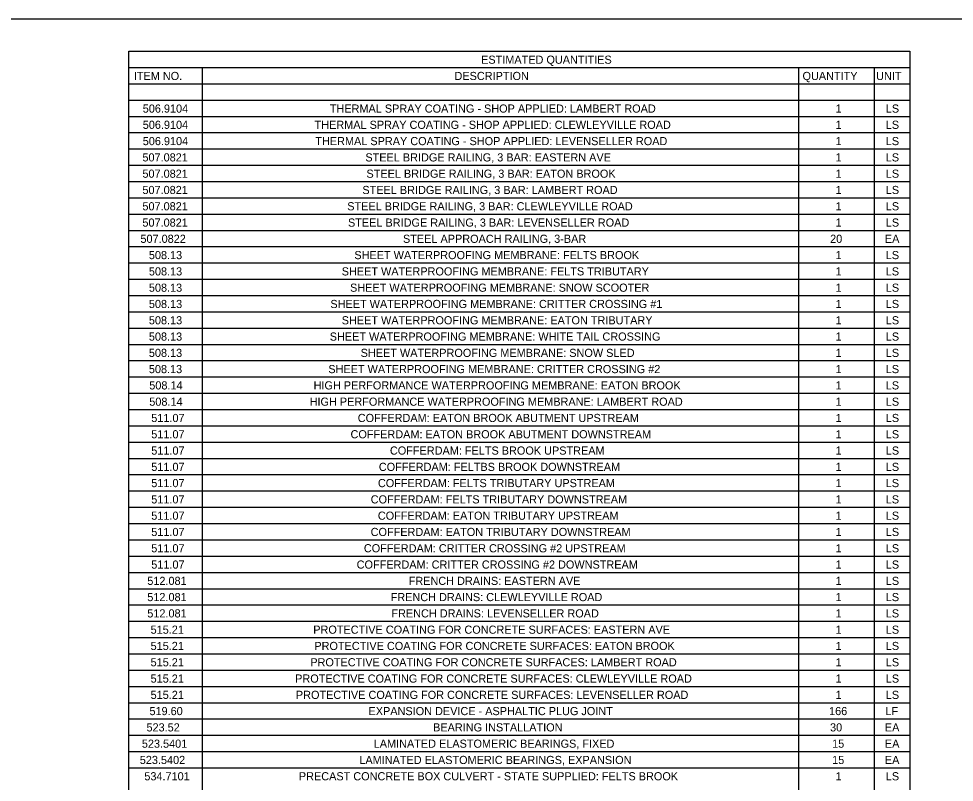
# Model space of a CAD drawing. Extents: x -18.7 to 5.6, y -2.7 to 5.1.
# Drawn here: x -16.637 to -15.505, y 3.091 to 4.014 of the extents above; entities that cross this region are included whole.
import ezdxf

# ---------------------------------------------------------------- set-up
doc = ezdxf.new("R2010")
doc.units = 0
doc.layers.add('ANNOTATION', color=7, linetype='Continuous')
doc.layers.add('BORDER', color=7, linetype='Continuous')

msp = doc.modelspace()

# ---------------------------------------------------------------- linework, layer by layer
at = {"layer": 'ANNOTATION'}
msp.add_lwpolyline([(-17.663, 4.0141), (-13.3075, 4.0141), (-13.3075, 2.1719), (-17.663, 2.1719)], close=True, dxfattribs=at)
at = {"layer": 'BORDER'}
for p, q in [((-16.5036, 3.9551), (-15.5593, 3.9551)), ((-16.415, 3.9551), (-16.415, 2.2424)), ((-15.6937, 3.9551), (-15.6937, 2.2424)), ((-15.6023, 3.9551), (-15.6023, 2.2424)), ((-16.5036, 3.9354), (-15.5593, 3.9354)), ((-16.5036, 3.9157), (-15.5593, 3.9157)), ((-16.5036, 3.896), (-15.5593, 3.896)), ((-16.5036, 3.8764), (-15.5593, 3.8764)), ((-16.5036, 3.8567), (-15.5593, 3.8567)), ((-16.5036, 3.837), (-15.5593, 3.837)), ((-16.5036, 3.8173), (-15.5593, 3.8173)), ((-16.5036, 3.7976), (-15.5593, 3.7976)), ((-16.5036, 3.7779), (-15.5593, 3.7779)), ((-16.5036, 3.7582), (-15.5593, 3.7582)), ((-16.5036, 3.7386), (-15.5593, 3.7386)), ((-16.5036, 3.7189), (-15.5593, 3.7189)), ((-16.5036, 3.6992), (-15.5593, 3.6992)), ((-16.5036, 3.6795), (-15.5593, 3.6795)), ((-16.5036, 3.6598), (-15.5593, 3.6598)), ((-16.5036, 3.6401), (-15.5593, 3.6401)), ((-16.5036, 3.6204), (-15.5593, 3.6204)), ((-16.5036, 3.6008), (-15.5593, 3.6008)), ((-16.5036, 3.5811), (-15.5593, 3.5811)), ((-16.5036, 3.5614), (-15.5593, 3.5614)), ((-16.5036, 3.5417), (-15.5593, 3.5417)), ((-16.5036, 3.522), (-15.5593, 3.522)), ((-16.5036, 3.5023), (-15.5593, 3.5023)), ((-16.5036, 3.4826), (-15.5593, 3.4826)), ((-16.5036, 3.463), (-15.5593, 3.463)), ((-16.5036, 3.4433), (-15.5593, 3.4433)), ((-16.5036, 3.4236), (-15.5593, 3.4236)), ((-16.5036, 3.4039), (-15.5593, 3.4039)), ((-16.5036, 3.3842), (-15.5593, 3.3842)), ((-16.5036, 3.3645), (-15.5593, 3.3645)), ((-16.5036, 3.3448), (-15.5593, 3.3448)), ((-16.5036, 3.3251), (-15.5593, 3.3251)), ((-16.5036, 3.3055), (-15.5593, 3.3055)), ((-16.5036, 3.2858), (-15.5593, 3.2858)), ((-16.5036, 3.2661), (-15.5593, 3.2661)), ((-16.5036, 3.2464), (-15.5593, 3.2464)), ((-16.5036, 3.2267), (-15.5593, 3.2267)), ((-16.5036, 3.207), (-15.5593, 3.207)), ((-16.5036, 3.1873), (-15.5593, 3.1873)), ((-16.5036, 3.1677), (-15.5593, 3.1677)), ((-16.5036, 3.148), (-15.5593, 3.148)), ((-16.5036, 3.1283), (-15.5593, 3.1283)), ((-16.5036, 3.1086), (-15.5593, 3.1086))]:
    msp.add_line(p, q, dxfattribs=at)
msp.add_lwpolyline([(-16.5036, 3.9748), (-15.5593, 3.9748), (-15.5593, 2.2424), (-16.5036, 2.2424)], close=True, dxfattribs=at)

# ---------------------------------------------------------------- texts
at = {"layer": 'ANNOTATION'}
for s, height, p in [('506.9104', 0.00984, (-16.4869, 3.9006)), ('THERMAL SPRAY COATING - SHOP APPLIED: LAMBERT ROAD', 0.009843, (-16.2607, 3.9006)), ('1', 0.00984, (-15.649, 3.9006)), ('LS', 0.00984, (-15.5883, 3.9006)), ('506.9104', 0.00984, (-16.4869, 3.881)), ('THERMAL SPRAY COATING - SHOP APPLIED: CLEWLEYVILLE ROAD', 0.009843, (-16.2791, 3.881)), ('1', 0.00984, (-15.649, 3.881)), ('LS', 0.00984, (-15.5883, 3.881)), ('506.9104', 0.00984, (-16.4869, 3.8613)), ('THERMAL SPRAY COATING - SHOP APPLIED: LEVENSELLER ROAD', 0.009843, (-16.2782, 3.8613)), ('1', 0.00984, (-15.649, 3.8613)), ('LS', 0.00984, (-15.5883, 3.8613)), ('507.0821', 0.00984, (-16.4873, 3.8416)), ('STEEL BRIDGE RAILING, 3 BAR: EASTERN AVE', 0.009843, (-16.2177, 3.8416)), ('1', 0.00984, (-15.649, 3.8416)), ('LS', 0.00984, (-15.5883, 3.8416)), ('507.0821', 0.00984, (-16.4873, 3.8219)), ('STEEL BRIDGE RAILING, 3 BAR: EATON BROOK', 0.009843, (-16.2164, 3.8219)), ('1', 0.00984, (-15.649, 3.8219)), ('LS', 0.00984, (-15.5883, 3.8219)), ('507.0821', 0.00984, (-16.4873, 3.8022)), ('STEEL BRIDGE RAILING, 3 BAR: LAMBERT ROAD', 0.009843, (-16.2213, 3.8022)), ('1', 0.00984, (-15.649, 3.8022)), ('LS', 0.00984, (-15.5883, 3.8022)), ('507.0821', 0.00984, (-16.4873, 3.7825)), ('STEEL BRIDGE RAILING, 3 BAR: CLEWLEYVILLE ROAD', 0.009843, (-16.2396, 3.7825)), ('1', 0.00984, (-15.649, 3.7825)), ('LS', 0.00984, (-15.5883, 3.7825)), ('507.0821', 0.00984, (-16.4873, 3.7628)), ('STEEL BRIDGE RAILING, 3 BAR: LEVENSELLER ROAD', 0.009843, (-16.2387, 3.7628)), ('1', 0.00984, (-15.649, 3.7628)), ('LS', 0.00984, (-15.5883, 3.7628)), ('507.0822', 0.00984, (-16.4897, 3.7432)), ('STEEL APPROACH RAILING, 3-BAR', 0.009843, (-16.1722, 3.7432)), ('20', 0.00984, (-15.6556, 3.7432)), ('EA', 0.00984, (-15.5894, 3.7432)), ('508.13', 0.00984, (-16.4795, 3.7235)), ('SHEET WATERPROOFING MEMBRANE: FELTS BROOK', 0.009843, (-16.231, 3.7235)), ('1', 0.00984, (-15.649, 3.7235)), ('LS', 0.00984, (-15.5883, 3.7235)), ('508.13', 0.00984, (-16.4795, 3.7038)), ('SHEET WATERPROOFING MEMBRANE: FELTS TRIBUTARY', 0.009843, (-16.2463, 3.7038)), ('1', 0.00984, (-15.649, 3.7038)), ('LS', 0.00984, (-15.5883, 3.7038)), ('508.13', 0.00984, (-16.4795, 3.6841)), ('SHEET WATERPROOFING MEMBRANE: SNOW SCOOTER', 0.009843, (-16.2362, 3.6841)), ('1', 0.00984, (-15.649, 3.6841)), ('LS', 0.00984, (-15.5883, 3.6841)), ('508.13', 0.00984, (-16.4795, 3.6644)), ('SHEET WATERPROOFING MEMBRANE: CRITTER CROSSING #1', 0.009843, (-16.26, 3.6644)), ('1', 0.00984, (-15.649, 3.6644)), ('LS', 0.00984, (-15.5883, 3.6644)), ('508.13', 0.00984, (-16.4795, 3.6447)), ('SHEET WATERPROOFING MEMBRANE: EATON TRIBUTARY', 0.009843, (-16.2463, 3.6447)), ('LS', 0.00984, (-15.5883, 3.6447)), ('1', 0.00984, (-15.649, 3.6447)), ('508.13', 0.00984, (-16.4795, 3.625)), ('SHEET WATERPROOFING MEMBRANE: WHITE TAIL CROSSING', 0.009843, (-16.2608, 3.625)), ('1', 0.00984, (-15.649, 3.625)), ('LS', 0.00984, (-15.5883, 3.625)), ('508.13', 0.00984, (-16.4795, 3.6053)), ('SHEET WATERPROOFING MEMBRANE: SNOW SLED', 0.009843, (-16.2234, 3.6053)), ('1', 0.00984, (-15.649, 3.6053)), ('LS', 0.00984, (-15.5883, 3.6053)), ('508.13', 0.00984, (-16.4795, 3.5857)), ('SHEET WATERPROOFING MEMBRANE: CRITTER CROSSING #2', 0.009843, (-16.2625, 3.5857)), ('1', 0.00984, (-15.649, 3.5857)), ('LS', 0.00984, (-15.5883, 3.5857)), ('508.14', 0.00984, (-16.479, 3.566)), ('HIGH PERFORMANCE WATERPROOFING MEMBRANE: EATON BROOK', 0.009843, (-16.2803, 3.566)), ('1', 0.00984, (-15.649, 3.566)), ('LS', 0.00984, (-15.5883, 3.566)), ('508.14', 0.00984, (-16.479, 3.5463)), ('HIGH PERFORMANCE WATERPROOFING MEMBRANE: LAMBERT ROAD', 0.009843, (-16.2851, 3.5463)), ('1', 0.00984, (-15.649, 3.5463)), ('LS', 0.00984, (-15.5883, 3.5463)), ('511.07', 0.00984, (-16.4766, 3.5266)), ('COFFERDAM: EATON BROOK ABUTMENT UPSTREAM', 0.009843, (-16.2269, 3.5266)), ('1', 0.00984, (-15.649, 3.5266)), ('LS', 0.00984, (-15.5883, 3.5266)), ('511.07', 0.00984, (-16.4766, 3.5069)), ('COFFERDAM: EATON BROOK ABUTMENT DOWNSTREAM', 0.009843, (-16.2356, 3.5069)), ('1', 0.00984, (-15.649, 3.5069)), ('LS', 0.00984, (-15.5883, 3.5069)), ('511.07', 0.00984, (-16.4766, 3.4872)), ('COFFERDAM: FELTS BROOK UPSTREAM', 0.009843, (-16.188, 3.4872)), ('1', 0.00984, (-15.649, 3.4872)), ('LS', 0.00984, (-15.5883, 3.4872)), ('511.07', 0.00984, (-16.4766, 3.4675)), ('COFFERDAM: FELTBS BROOK DOWNSTREAM', 0.009843, (-16.2014, 3.4675)), ('1', 0.00984, (-15.649, 3.4675)), ('LS', 0.00984, (-15.5883, 3.4675)), ('511.07', 0.00984, (-16.4766, 3.4479)), ('COFFERDAM: FELTS TRIBUTARY UPSTREAM', 0.009843, (-16.2025, 3.4479)), ('1', 0.00984, (-15.649, 3.4479)), ('LS', 0.00984, (-15.5883, 3.4479)), ('511.07', 0.00984, (-16.4766, 3.4282)), ('COFFERDAM: FELTS TRIBUTARY DOWNSTREAM', 0.009843, (-16.2112, 3.4282)), ('1', 0.00984, (-15.649, 3.4282)), ('LS', 0.00984, (-15.5883, 3.4282)), ('511.07', 0.00984, (-16.4766, 3.4085)), ('COFFERDAM: EATON TRIBUTARY UPSTREAM', 0.009843, (-16.2026, 3.4085)), ('1', 0.00984, (-15.649, 3.4085)), ('LS', 0.00984, (-15.5883, 3.4085)), ('511.07', 0.00984, (-16.4766, 3.3888)), ('COFFERDAM: EATON TRIBUTARY DOWNSTREAM', 0.009843, (-16.2113, 3.3888)), ('1', 0.00984, (-15.649, 3.3888)), ('LS', 0.00984, (-15.5883, 3.3888)), ('511.07', 0.00984, (-16.4766, 3.3691)), ('COFFERDAM: CRITTER CROSSING #2 UPSTREAM', 0.009843, (-16.2195, 3.3691)), ('1', 0.00984, (-15.649, 3.3691)), ('LS', 0.00984, (-15.5883, 3.3691)), ('511.07', 0.00984, (-16.4766, 3.3494)), ('COFFERDAM: CRITTER CROSSING #2 DOWNSTREAM', 0.009843, (-16.2282, 3.3494)), ('1', 0.00984, (-15.649, 3.3494)), ('LS', 0.00984, (-15.5883, 3.3494)), ('512.081', 0.00984, (-16.4814, 3.3297)), ('FRENCH DRAINS: EASTERN AVE', 0.009843, (-16.1653, 3.3297)), ('1', 0.00984, (-15.649, 3.3297)), ('LS', 0.00984, (-15.5883, 3.3297)), ('512.081', 0.00984, (-16.4814, 3.3101)), ('FRENCH DRAINS: CLEWLEYVILLE ROAD', 0.009843, (-16.1871, 3.3101)), ('1', 0.00984, (-15.649, 3.3101)), ('LS', 0.00984, (-15.5883, 3.3101)), ('512.081', 0.00984, (-16.4814, 3.2904)), ('FRENCH DRAINS: LEVENSELLER ROAD', 0.009843, (-16.1862, 3.2904)), ('1', 0.00984, (-15.649, 3.2904)), ('LS', 0.00984, (-15.5883, 3.2904)), ('515.21', 0.00984, (-16.4774, 3.2707)), ('PROTECTIVE COATING FOR CONCRETE SURFACES: EASTERN AVE', 0.009843, (-16.2807, 3.2707)), ('1', 0.00984, (-15.649, 3.2707)), ('LS', 0.00984, (-15.5883, 3.2707)), ('515.21', 0.00984, (-16.4774, 3.251)), ('PROTECTIVE COATING FOR CONCRETE SURFACES: EATON BROOK', 0.009843, (-16.2794, 3.251)), ('1', 0.00984, (-15.649, 3.251)), ('LS', 0.00984, (-15.5883, 3.251)), ('515.21', 0.00984, (-16.4774, 3.2313)), ('PROTECTIVE COATING FOR CONCRETE SURFACES: LAMBERT ROAD', 0.009843, (-16.2843, 3.2313)), ('1', 0.00984, (-15.649, 3.2313)), ('LS', 0.00984, (-15.5883, 3.2313)), ('515.21', 0.00984, (-16.4774, 3.2116)), ('PROTECTIVE COATING FOR CONCRETE SURFACES: CLEWLEYVILLE ROAD', 0.009843, (-16.3026, 3.2116)), ('1', 0.00984, (-15.649, 3.2116)), ('LS', 0.00984, (-15.5883, 3.2116)), ('515.21', 0.00984, (-16.4774, 3.1919)), ('PROTECTIVE COATING FOR CONCRETE SURFACES: LEVENSELLER ROAD', 0.009843, (-16.3017, 3.1919)), ('1', 0.00984, (-15.649, 3.1919)), ('LS', 0.00984, (-15.5883, 3.1919)), ('519.60', 0.00984, (-16.4788, 3.1723)), ('EXPANSION DEVICE - ASPHALTIC PLUG JOINT', 0.009843, (-16.2139, 3.1723)), ('166', 0.00984, (-15.6569, 3.1723)), ('LF', 0.00984, (-15.5887, 3.1723)), ('523.52', 0.00984, (-16.4824, 3.1526)), ('BEARING INSTALLATION', 0.009843, (-16.1358, 3.1526)), ('30', 0.00984, (-15.6557, 3.1526)), ('EA', 0.00984, (-15.5894, 3.1526)), ('523.5401', 0.00984, (-16.488, 3.1329)), ('LAMINATED ELASTOMERIC BEARINGS, FIXED', 0.009843, (-16.2076, 3.1329)), ('15', 0.00984, (-15.6532, 3.1329)), ('EA', 0.00984, (-15.5894, 3.1329)), ('523.5402', 0.00984, (-16.4905, 3.1132)), ('LAMINATED ELASTOMERIC BEARINGS, EXPANSION', 0.009843, (-16.225, 3.1132)), ('15', 0.00984, (-15.6532, 3.1132)), ('EA', 0.00984, (-15.5894, 3.1132)), ('534.7101', 0.00984, (-16.485, 3.0935)), ('PRECAST CONCRETE BOX CULVERT - STATE SUPPLIED: FELTS BROOK', 0.009843, (-16.2981, 3.0935)), ('1', 0.00984, (-15.649, 3.0935)), ('LS', 0.00984, (-15.5883, 3.0935))]:
    msp.add_text(s, height=height, dxfattribs=at).set_placement(p)
at = {"layer": 'BORDER'}
for s, height, p in [('ESTIMATED QUANTITIES', 0.009843, (-16.0777, 3.9597)), ('ITEM NO.', 0.00984, (-16.4977, 3.94)), ('DESCRIPTION', 0.009843, (-16.1099, 3.94)), ('QUANTITY', 0.00984, (-15.689, 3.94)), ('UNIT', 0.00984, (-15.6, 3.94))]:
    msp.add_text(s, height=height, dxfattribs=at).set_placement(p)

doc.saveas('drawing.dxf')
